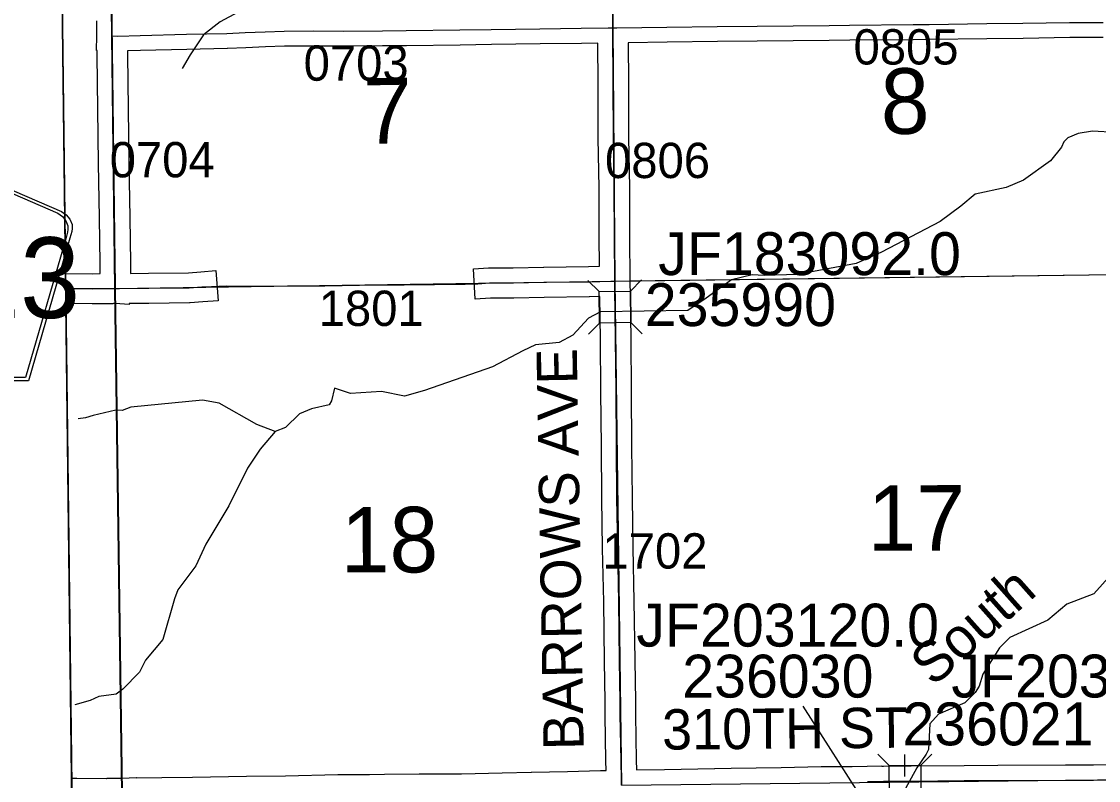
# Model space of a CAD drawing. Extents: x 23.6 to 68.7, y -63 to -29.
# Drawn here: x 32.621 to 34.757, y -54.733 to -53.228 of the extents above; entities that cross this region are included whole.
import ezdxf

# ---------------------------------------------------------------- set-up
doc = ezdxf.new("R2010")
doc.units = 0
for name, color, linetype in [('tdCoClipBndry', 7, 'Continuous'), ('tdCoCoBndry', 7, 'Continuous'), ('tdCoCoBndryPart', 7, 'Continuous'), ('tdCoHydroRiver', 7, 'Continuous'), ('tdCoHydroTxtLg', 7, 'Continuous'), ('tdCoSecRdNmbr', 7, 'Continuous'), ('tdCoSecRdTxt', 7, 'Continuous'), ('tdCoSecRteBand', 7, 'Continuous'), ('tdCoSecRteCL', 7, 'Continuous'), ('tdCoSectLine', 7, 'Continuous'), ('tdCoSectLinePart', 7, 'Continuous'), ('tdCoSectNmbr', 7, 'Continuous'), ('tdCoShieldCoRte', 7, 'Continuous'), ('tdCoStrucSec', 7, 'Continuous'), ('tdCoStrucSecCoName', 7, 'Continuous'), ('tdCoStrucSecFHWANum', 7, 'Continuous'), ('tdCoSurfAsphalt', 7, 'Continuous'), ('tdCoSurfGravel', 7, 'Continuous'), ('tdCoSurfLNO', 7, 'Continuous'), ('tdCoTwpBndryShd', 7, 'Continuous')]:
    doc.layers.add(name, color=color, linetype=linetype)

msp = doc.modelspace()

# ---------------------------------------------------------------- linework, layer by layer
at = {"layer": 'tdCoClipBndry'}
msp.add_lwpolyline([(56.8227, -57.553), (51.8233, -57.6334), (46.8056, -57.7041), (45.8081, -57.7131), (44.8328, -57.735), (43.8446, -57.7356), (42.8125, -57.7502), (36.856, -57.8104), (34.8462, -57.8398), (33.8615, -57.8433), (32.8589, -57.8556), (32.833, -57.8525), (32.8013, -57.8383), (32.7717, -57.8067), (32.7614, -57.7827), (32.7577, -57.7569), (32.6839, -51.7283), (32.6474, -49.7276), (32.6233, -45.7459), (32.6113, -44.7492), (32.588, -43.7493), (32.587, -43.0064), (32.5923, -42.7484), (32.5183, -35.7733)], dxfattribs=at)
at = {"layer": 'tdCoCoBndry'}
for p, q in [((32.8066, -53.7572), (32.7948, -52.7546)), ((32.7948, -52.7546), (32.8066, -53.7572)), ((32.8205, -54.758), (32.8066, -53.7572)), ((32.8066, -53.7572), (32.8205, -54.758))]:
    msp.add_line(p, q, dxfattribs=at)
for points in [[(32.6718, -40.7503), (32.6807, -41.745), (32.6923, -42.7489), (32.6875, -42.9908), (32.687, -43.0063), (32.6879, -43.7492), (32.7112, -44.7475), (32.7232, -45.7449), (32.73, -46.7351), (32.7344, -47.7196), (32.7414, -48.7221), (32.7473, -49.7257), (32.7682, -50.7257), (32.7838, -51.7268), (32.7945, -52.7546), (32.8063, -53.7572), (32.8202, -54.758), (32.8346, -55.7561), (32.8426, -56.756), (32.8576, -57.7557)], [(36.8552, -57.7104), (35.8554, -57.7251), (34.8462, -57.7399), (33.861, -57.7434), (32.858, -57.7557), (32.843, -56.756), (32.8349, -55.7561), (32.8205, -54.758), (32.8066, -53.7572), (32.7948, -52.7546), (32.7842, -51.7268), (32.7685, -50.7257), (32.7477, -49.7257), (32.7417, -48.7221), (32.7347, -47.7196), (32.7303, -46.7351), (32.7236, -45.745), (32.7116, -44.7475), (32.6883, -43.7492), (32.6873, -43.0063), (32.6879, -42.9908), (32.6927, -42.7489), (32.6811, -41.7451), (32.6722, -40.7503)], [(32.6474, -49.7276), (32.6839, -51.7283), (32.7577, -57.7564), (32.858, -57.7557), (32.843, -56.756), (32.8349, -55.7561), (32.8205, -54.758), (32.8066, -53.7572), (32.7948, -52.7546), (32.7842, -51.7268), (32.7685, -50.7257)]]:
    msp.add_lwpolyline(points, dxfattribs=at)
at = {"layer": 'tdCoCoBndryPart'}
msp.add_lwpolyline([(32.8067, -53.7876), (32.8198, -54.7285)], dxfattribs=at)
at = {"layer": 'tdCoHydroRiver'}
for points in [[(33.736, -52.7747), (33.7282, -52.7905), (33.7253, -52.8174), (33.7176, -52.8459), (33.6881, -52.9029), (33.6677, -52.9268), (33.5878, -53), (33.58, -53.0111), (33.5439, -53.0399), (33.4386, -53.0991), (33.3725, -53.1154), (33.2085, -53.1357), (33.1643, -53.1455), (33.1455, -53.1551), (33.1204, -53.1774), (33.0779, -53.1951), (33.015, -53.2288), (32.9821, -53.2543), (32.9556, -53.294), (32.94, -53.321)], [(34.8369, -53.4509), (34.7453, -53.4454), (34.7169, -53.4503), (34.6965, -53.4584)], [(34.6965, -53.4584), (34.6886, -53.4663), (34.684, -53.4774), (34.6621, -53.5044), (34.6087, -53.5427), (34.5741, -53.5572), (34.5127, -53.5704), (34.4845, -53.5943), (34.4436, -53.6246), (34.3273, -53.6855), (34.277, -53.708), (34.1604, -53.7295), (34.0941, -53.7316), (34.0704, -53.7302), (34.0294, -53.74), (33.9792, -53.7767), (33.9431, -53.8007), (33.7695, -53.8036), (33.7459, -53.8165), (33.7146, -53.8499), (33.6879, -53.8643), (33.6406, -53.8694), (33.6154, -53.8807), (33.5557, -53.9127), (33.4203, -53.9596), (33.3809, -53.9709), (33.3351, -53.9618), (33.2735, -53.9655), (33.2561, -53.9593), (33.2419, -53.9547), (33.2358, -53.98), (33.2311, -53.9879), (33.1964, -53.9961), (33.1728, -54.0058), (33.1446, -54.0328), (33.1242, -54.0409)], [(33.1242, -54.0409), (33.0878, -54.027), (33.0132, -53.985), (32.98, -53.9789), (32.8381, -53.9927), (32.8207, -53.9991), (32.8082, -53.9988)], [(32.8082, -53.9988), (32.7633, -54.0094), (32.7483, -54.0137), (32.7333, -54.0158)], [(33.1242, -54.0409), (33.0945, -54.0759), (33.0695, -54.1139), (33.0322, -54.1884), (32.9871, -54.2646), (32.9669, -54.3074), (32.931, -54.355), (32.9248, -54.3724), (32.9017, -54.4531), (32.8673, -54.4944), (32.8549, -54.5182), (32.822, -54.5516), (32.8091, -54.5619)], [(34.7823, -54.3243), (34.7479, -54.3625), (34.6944, -54.3834), (34.6568, -54.4153), (34.5813, -54.4491), (34.5609, -54.4698), (34.5282, -54.5221), (34.5205, -54.5459), (34.5127, -54.5585), (34.4924, -54.5792), (34.4404, -54.6017), (34.4232, -54.6208), (34.4205, -54.6714), (34.4158, -54.6809), (34.3971, -54.7079), (34.3675, -54.7618)], [(32.8091, -54.5619), (32.7742, -54.5661), (32.7571, -54.5746), (32.7271, -54.5832)]]:
    msp.add_lwpolyline(points, dxfattribs=at)
at = {"layer": 'tdCoSecRteBand'}
for points in [[(32.7083, -53.7274), (32.7616, -53.728), (32.7773, -53.7278), (32.7772, -53.7079), (32.7758, -53.6173), (32.7738, -53.5098), (32.7738, -53.5097), (32.7738, -53.5096), (32.7726, -53.4021), (32.7712, -53.2946), (32.7711, -53.2869), (32.7711, -53.2855), (32.7697, -53.2854), (32.7707, -53.2562), (32.7704, -53.2269)], [(32.7206, -54.7285), (32.7302, -54.7285), (32.7304, -54.7285), (32.7306, -54.7285), (32.7896, -54.729), (32.7896, -54.729), (32.7902, -54.7289), (32.7902, -54.7284), (32.8199, -54.728), (32.8495, -54.7271), (32.8495, -54.7271), (32.8496, -54.7271), (32.8496, -54.7277), (32.8994, -54.7272), (32.9601, -54.7262), (33.0674, -54.7244), (33.0675, -54.7244), (33.0676, -54.7244), (33.1448, -54.7236), (33.2487, -54.7213), (33.2489, -54.7213), (33.2491, -54.7213), (33.2815, -54.721), (33.3114, -54.7208), (33.3413, -54.7204), (33.3413, -54.7204), (33.4097, -54.7196), (33.41, -54.7196), (33.4102, -54.7196), (33.4938, -54.7198), (33.5748, -54.7178), (33.5748, -54.7178), (33.5748, -54.7178), (33.6322, -54.7164), (33.6324, -54.7164), (33.6325, -54.7164), (33.7039, -54.7153), (33.7694, -54.7133), (33.7694, -54.7133), (33.7695, -54.7133), (33.781, -54.713), (33.7805, -54.6937), (33.7805, -54.6936), (33.7805, -54.6936), (33.7788, -54.6032), (33.7787, -54.6028), (33.7787, -54.6024), (33.7789, -54.5765), (33.7776, -54.4962), (33.7776, -54.4961), (33.7776, -54.4961), (33.776, -54.3784), (33.7738, -54.273), (33.7738, -54.2729), (33.7738, -54.2728), (33.7722, -54.1736), (33.7722, -54.1735), (33.7722, -54.1734), (33.7715, -54.0708), (33.7705, -53.9613), (33.7695, -53.8582), (33.7685, -53.7733), (33.7475, -53.7739), (33.7473, -53.7739), (33.747, -53.7739), (33.6578, -53.7749), (33.5977, -53.7763), (33.5973, -53.7763), (33.597, -53.7763), (33.5523, -53.7763), (33.5512, -53.7764), (33.5213, -53.7783), (33.5175, -53.7184), (33.5474, -53.7165), (33.5495, -53.7164), (33.5504, -53.7163), (33.5514, -53.7163), (33.5966, -53.7163), (33.6566, -53.7149), (33.6568, -53.7149), (33.657, -53.7149), (33.7461, -53.7139), (33.7679, -53.7133), (33.7679, -53.7129), (33.7673, -53.6543), (33.7673, -53.6543), (33.7673, -53.6542), (33.7669, -53.5581), (33.7653, -53.4594), (33.7653, -53.4592), (33.7653, -53.4591), (33.7649, -53.3506), (33.7643, -53.2707), (33.7318, -53.2713), (33.7317, -53.2713), (33.7317, -53.2713), (33.65, -53.2725), (33.65, -53.2725), (33.65, -53.2725), (33.5533, -53.2738), (33.5533, -53.2738), (33.5533, -53.2738), (33.4913, -53.2746), (33.3848, -53.276), (33.3847, -53.276), (33.3847, -53.276), (33.3373, -53.2764), (33.3373, -53.2764), (33.3373, -53.2764), (33.2605, -53.277), (33.2604, -53.277), (33.2602, -53.277), (33.1994, -53.2768), (33.1428, -53.2772), (33.1053, -53.2782), (33.0662, -53.2799), (33.0661, -53.2799), (33.0661, -53.2799), (33.0296, -53.2815), (33.0293, -53.2815), (33.029, -53.2815), (32.9489, -53.2833), (32.8575, -53.2855), (32.8311, -53.2863), (32.8312, -53.2939), (32.8312, -53.2939), (32.8312, -53.2939), (32.8326, -53.4014), (32.8326, -53.4014), (32.8326, -53.4014), (32.8338, -53.5088), (32.8358, -53.6163), (32.8358, -53.6163), (32.8358, -53.6163), (32.8371, -53.7071), (32.8371, -53.7073), (32.8371, -53.7074), (32.8373, -53.7274), (32.8732, -53.7269), (32.8733, -53.7269), (32.8733, -53.7269), (32.9525, -53.726), (32.9766, -53.7242), (33.0065, -53.722), (33.011, -53.7818), (32.981, -53.784), (32.956, -53.7859), (32.9551, -53.786), (32.9542, -53.786), (32.874, -53.7869), (32.8347, -53.7874), (32.8345, -53.7891), (32.8066, -53.7872), (32.8041, -53.7874), (32.8033, -53.7874), (32.8025, -53.7875), (32.762, -53.788), (32.7617, -53.788), (32.7613, -53.788), (32.7091, -53.7874)], [(34.7669, -53.26), (34.7003, -53.2598), (34.6081, -53.2614), (34.608, -53.2614), (34.6079, -53.2614), (34.5363, -53.2622), (34.4217, -53.2636), (34.39, -53.264), (34.3899, -53.264), (34.3899, -53.264), (34.2641, -53.2652), (34.2235, -53.2658), (34.2234, -53.2658), (34.2233, -53.2658), (34.0805, -53.2669), (34.0017, -53.2679), (34.0017, -53.2679), (34.0017, -53.2679), (33.9018, -53.2691), (33.8243, -53.27), (33.8243, -53.27), (33.8243, -53.27), (33.8249, -53.3502), (33.8249, -53.3503), (33.8249, -53.3503), (33.8253, -53.4587), (33.8269, -53.5573), (33.8269, -53.5575), (33.8269, -53.5577), (33.8273, -53.6539), (33.8281, -53.7422), (33.8287, -53.7721), (33.8285, -53.7721), (33.8295, -53.8575), (33.8295, -53.8575), (33.8295, -53.8576), (33.8305, -53.9608), (33.8305, -53.9608), (33.8305, -53.9608), (33.8314, -54.0703), (33.8314, -54.0703), (33.8314, -54.0703), (33.8322, -54.1728), (33.8338, -54.2718), (33.836, -54.3773), (33.836, -54.3774), (33.836, -54.3775), (33.8376, -54.4952), (33.8389, -54.5759), (33.8389, -54.5762), (33.8389, -54.5766), (33.8388, -54.6024), (33.8405, -54.6923), (33.841, -54.7117), (33.8969, -54.7109), (33.996, -54.7091), (33.9961, -54.7091), (33.9962, -54.7091), (34.0291, -54.7087), (34.1281, -54.707), (34.2074, -54.7052), (34.2077, -54.7052), (34.2081, -54.7052), (34.2642, -54.7052), (34.2686, -54.7052), (34.2983, -54.7047), (34.328, -54.7037), (34.328, -54.7043), (34.3286, -54.7043), (34.3307, -54.7043), (34.3308, -54.7043), (34.331, -54.7043), (34.386, -54.704), (34.4909, -54.7032), (34.491, -54.7032), (34.491, -54.7032), (34.5579, -54.7028), (34.6918, -54.702), (34.6919, -54.702), (34.692, -54.702), (34.7474, -54.702), (34.8943, -54.6997)]]:
    msp.add_lwpolyline(points, dxfattribs=at)
at = {"layer": 'tdCoSecRteCL'}
for points in [[(32.8007, -53.2565), (32.7998, -53.1883), (32.7985, -53.0824), (32.7975, -52.975), (32.7961, -52.8667), (32.7949, -52.7616), (32.7939, -52.6641), (32.7926, -52.5588), (32.7914, -52.4576), (32.7896, -52.3498), (32.7884, -52.2737), (32.7888, -52.2569)], [(33.7941, -53.2403), (33.7934, -53.1567), (33.7922, -53.0441), (33.7916, -52.9421), (33.791, -52.8365), (33.7902, -52.7341), (33.7894, -52.6252), (33.7884, -52.5145), (33.7882, -52.493)], [(33.7941, -53.2403), (33.8021, -53.2403), (33.9015, -53.2391), (34.0013, -53.2379), (34.0802, -53.2369), (34.2231, -53.2358), (34.2637, -53.2352), (34.3896, -53.234), (34.4213, -53.2336), (34.536, -53.2322), (34.6076, -53.2314), (34.7001, -53.2298), (34.767, -53.23)], [(32.8007, -53.2565), (32.8121, -53.2569), (32.8567, -53.2555), (32.9482, -53.2533), (33.0283, -53.2515), (33.0648, -53.25), (33.1043, -53.2482), (33.1423, -53.2472), (33.1994, -53.2468), (33.2603, -53.247), (33.3371, -53.2464), (33.3844, -53.246), (33.4909, -53.2446), (33.5529, -53.2438), (33.6496, -53.2425), (33.7312, -53.2413), (33.7849, -53.2403), (33.7941, -53.2403)], [(33.7981, -53.7426), (33.7973, -53.6541), (33.7969, -53.5578), (33.7953, -53.4589), (33.7949, -53.3504), (33.7941, -53.2486), (33.7941, -53.2403)], [(32.8066, -53.7572), (32.8073, -53.746), (32.8071, -53.7076), (32.8058, -53.6168), (32.8038, -53.5093), (32.8026, -53.4018), (32.8012, -53.2942), (32.8007, -53.2565)], [(33.5493, -53.7464), (33.5514, -53.7463), (33.597, -53.7463), (33.6573, -53.7449), (33.7467, -53.7439), (33.7899, -53.7427), (33.7981, -53.7426)], [(33.8113, -54.7422), (33.8115, -54.7312), (33.8105, -54.693), (33.8087, -54.6026), (33.8089, -54.5764), (33.8076, -54.4957), (33.806, -54.3779), (33.8038, -54.2724), (33.8022, -54.1731), (33.8014, -54.0705), (33.8005, -53.961), (33.7995, -53.8579), (33.7983, -53.7576), (33.7981, -53.7426)], [(32.7087, -53.7574), (32.7617, -53.758), (32.8022, -53.7575), (32.8066, -53.7572)], [(32.8066, -53.7572), (32.8158, -53.7577), (32.8736, -53.7569), (32.9538, -53.756), (32.9788, -53.7541)], [(34.299, -54.7347), (34.3311, -54.7343), (34.3862, -54.734), (34.4912, -54.7332), (34.558, -54.7328), (34.692, -54.732), (34.7476, -54.732), (34.8948, -54.7297), (34.9372, -54.7289), (35.0976, -54.7291), (35.2363, -54.7279), (35.2866, -54.7283), (35.4622, -54.7269), (35.6538, -54.7249), (35.8005, -54.7233), (35.8156, -54.7235)]]:
    msp.add_lwpolyline(points, dxfattribs=at)
at = {"layer": 'tdCoSectLine'}
for points in [[(33.7899, -52.7341), (33.7978, -53.7426)], [(32.7945, -52.7546), (32.8063, -53.7572)], [(32.8063, -53.7572), (33.7978, -53.7426)], [(33.7978, -53.7426), (34.7885, -53.7294)], [(33.7978, -53.7426), (33.811, -54.7422)], [(32.7087, -53.7577), (32.8063, -53.7572)], [(32.8063, -53.7572), (32.8202, -54.758)], [(33.811, -54.7422), (34.8144, -54.7309)]]:
    msp.add_lwpolyline(points, dxfattribs=at)
at = {"layer": 'tdCoSectLinePart'}
for points in [[(33.8281, -53.7422), (34.7885, -53.7294)], [(32.8067, -53.7876), (32.8198, -54.7285)]]:
    msp.add_lwpolyline(points, dxfattribs=at)
at = {"layer": 'tdCoShieldCoRte'}
for points in [[(32.3954, -53.9402), (32.3135, -53.6573), (32.3096, -53.6441), (32.3089, -53.6382), (32.3089, -53.6304), (32.3131, -53.6201), (32.3204, -53.6116), (32.33, -53.6049), (32.4973, -53.5326), (32.5048, -53.531), (32.5152, -53.53), (32.5256, -53.531), (32.5331, -53.5326), (32.7004, -53.6049), (32.71, -53.6116), (32.7173, -53.6201), (32.7215, -53.6304), (32.7215, -53.6382), (32.7208, -53.6441), (32.7169, -53.6573), (32.635, -53.9402)], [(32.4013, -53.9338), (32.3216, -53.6586), (32.3178, -53.6459), (32.3171, -53.6403), (32.3171, -53.6328), (32.3212, -53.6229), (32.3282, -53.6147), (32.3374, -53.6083), (32.498, -53.5389), (32.5052, -53.5373), (32.5152, -53.5364), (32.5252, -53.5373), (32.5324, -53.5389), (32.693, -53.6083), (32.7022, -53.6147), (32.7092, -53.6229), (32.7133, -53.6328), (32.7133, -53.6403), (32.7126, -53.6459), (32.7088, -53.6586), (32.6291, -53.9338)]]:
    msp.add_lwpolyline(points, close=True, dxfattribs=at)
at = {"layer": 'tdCoStrucSec'}
for p, q in [((33.7667, -53.7633), (33.7443, -53.7414)), ((33.8293, -53.7625), (33.8512, -53.7401)), ((33.7675, -53.8258), (33.7456, -53.8482)), ((33.8301, -53.8251), (33.8524, -53.847)), ((34.3423, -54.7029), (34.32, -54.6809)), ((34.4049, -54.7026), (34.4269, -54.6804))]:
    msp.add_line(p, q, dxfattribs=at)
for points in [[(33.7675, -53.8258), (33.7667, -53.7633), (33.8293, -53.7625), (33.8301, -53.8251)], [(34.3423, -54.7029), (34.4049, -54.7026), (34.4052, -54.7652), (34.3426, -54.7655)]]:
    msp.add_lwpolyline(points, close=True, dxfattribs=at)
at = {"layer": 'tdCoStrucSecFHWANum'}
for p, q in [((34.1709, -54.5855), (34.298, -54.7841)), ((34.3724, -54.6817), (34.3724, -54.7251))]:
    msp.add_line(p, q, dxfattribs=at)
at = {"layer": 'tdCoSurfAsphalt'}
msp.add_lwpolyline([(34.4912, -54.7332), (34.558, -54.7328), (34.692, -54.732), (34.7476, -54.732), (34.8948, -54.7297), (34.9372, -54.7289), (35.0976, -54.7291), (35.2363, -54.7279), (35.2866, -54.7283), (35.4622, -54.7269), (35.6538, -54.7249), (35.8005, -54.7233), (35.8156, -54.7235), (35.8485, -54.7237), (35.9953, -54.7218), (36.0479, -54.7212), (36.2097, -54.7198), (36.3648, -54.7178), (36.4107, -54.7176), (36.5587, -54.7153), (36.7371, -54.7121)], dxfattribs=at)
at = {"layer": 'tdCoSurfGravel'}
for points in [[(32.8066, -53.7572), (32.8073, -53.746), (32.8071, -53.7076), (32.8058, -53.6168), (32.8038, -53.5093), (32.8026, -53.4018), (32.8012, -53.2942), (32.8007, -53.2565), (32.7998, -53.1883), (32.7985, -53.0824), (32.7975, -52.975), (32.7961, -52.8667), (32.7949, -52.7616), (32.7939, -52.6641), (32.7926, -52.5588), (32.7914, -52.4576), (32.7896, -52.3498), (32.7884, -52.2737), (32.7888, -52.2569)], [(33.8113, -54.7422), (33.8115, -54.7312), (33.8105, -54.693), (33.8087, -54.6026), (33.8089, -54.5764), (33.8076, -54.4957), (33.806, -54.3779), (33.8038, -54.2724), (33.8022, -54.1731), (33.8014, -54.0705), (33.8005, -53.961), (33.7995, -53.8579), (33.7983, -53.7576), (33.7981, -53.7426), (33.7973, -53.6541), (33.7969, -53.5578), (33.7953, -53.4589), (33.7949, -53.3504), (33.7941, -53.2486), (33.7941, -53.2403), (33.7934, -53.1567)], [(32.8007, -53.2565), (32.8121, -53.2569), (32.8567, -53.2555), (32.9482, -53.2533), (33.0283, -53.2515), (33.0648, -53.25), (33.1043, -53.2482), (33.1423, -53.2472), (33.1994, -53.2468), (33.2603, -53.247), (33.3371, -53.2464), (33.3844, -53.246), (33.4909, -53.2446), (33.5529, -53.2438), (33.6496, -53.2425), (33.7312, -53.2413), (33.7849, -53.2403), (33.7941, -53.2403), (33.8021, -53.2403), (33.9015, -53.2391), (34.0013, -53.2379), (34.0802, -53.2369), (34.2231, -53.2358), (34.2637, -53.2352), (34.3896, -53.234), (34.4213, -53.2336), (34.536, -53.2322), (34.6076, -53.2314), (34.7001, -53.2298), (34.767, -53.23)], [(33.5493, -53.7464), (33.5514, -53.7463), (33.597, -53.7463), (33.6573, -53.7449), (33.7467, -53.7439), (33.7899, -53.7427), (33.7981, -53.7426)], [(32.7087, -53.7574), (32.7617, -53.758), (32.8022, -53.7575), (32.8066, -53.7572)], [(32.8066, -53.7572), (32.8158, -53.7577), (32.8736, -53.7569), (32.9538, -53.756), (32.9788, -53.7541)]]:
    msp.add_lwpolyline(points, dxfattribs=at)
at = {"layer": 'tdCoSurfLNO'}
for p, q in [((33.5265, -53.7479), (33.5493, -53.7464)), ((32.9788, -53.7541), (32.983, -53.7538)), ((32.983, -53.7538), (33.0278, -53.7522)), ((33.0278, -53.7522), (33.0789, -53.7526)), ((33.0789, -53.7526), (33.1489, -53.752)), ((33.1489, -53.752), (33.2231, -53.7518)), ((33.2231, -53.7518), (33.3257, -53.7504)), ((33.3257, -53.7504), (33.38, -53.7498)), ((33.38, -53.7498), (33.5011, -53.7485)), ((33.5011, -53.7485), (33.5265, -53.7479))]:
    msp.add_line(p, q, dxfattribs=at)
at = {"layer": 'tdCoTwpBndryShd'}
msp.add_lwpolyline([(32.8576, -57.7557), (32.8426, -56.756), (32.8346, -55.7561), (32.8202, -54.758), (32.8063, -53.7572), (32.7945, -52.7546), (32.7838, -51.7268), (32.7682, -50.7257), (32.7473, -49.7257), (32.7414, -48.7221), (32.7344, -47.7196), (32.73, -46.7351), (32.7232, -45.7449), (32.7112, -44.7475), (32.6879, -43.7492), (32.687, -43.0063), (32.6875, -42.9908), (32.6923, -42.7489), (32.6807, -41.745), (32.6718, -40.7503)], dxfattribs=at)

# ---------------------------------------------------------------- texts
at = {"layer": 'tdCoHydroTxtLg'}
msp.add_text('South', height=0.08, rotation=41.6956, dxfattribs=at).set_placement((34.4297, -54.5487))
at = {"layer": 'tdCoSecRdNmbr'}
for s, rotation, p in [('0805', 0.0271, (34.2716, -53.3133)), ('0703', 0.0263, (33.1808, -53.3454)), ('0704', 0.026, (32.7961, -53.537)), ('0806', 0.0267, (33.7787, -53.5385)), ('1801', 0.0263, (33.2107, -53.8317)), ('1702', 0.0267, (33.7736, -54.3128))]:
    msp.add_text(s, height=0.07, rotation=rotation, dxfattribs=at).set_placement(p)
at = {"layer": 'tdCoSecRdTxt'}
for s, rotation, p in [('BARROWS AVE', 91, (33.7365, -54.672)), ('310TH ST', 0.4602, (33.8921, -54.6718))]:
    msp.add_text(s, height=0.08, rotation=rotation, dxfattribs=at).set_placement(p)
at = {"layer": 'tdCoSectNmbr'}
for s, rotation, p in [('8', 1.027, (34.3264, -53.4516)), ('7', 1.0263, (33.3001, -53.4707)), ('17', 0.027, (34.2993, -54.2774)), ('18', 0.0262, (33.2545, -54.3204))]:
    msp.add_text(s, height=0.13, rotation=rotation, dxfattribs=at).set_placement(p)
at = {"layer": 'tdCoShieldCoRte'}
msp.add_text('T23', height=0.16, dxfattribs=at).set_placement((32.3686, -53.8159))
at = {"layer": 'tdCoStrucSecCoName'}
for s, p in [('JF183092.0', (33.8842, -53.7308)), ('JF203120.0', (33.8408, -54.4674)), ('JF203118.0', (34.4657, -54.5683))]:
    msp.add_text(s, height=0.085, dxfattribs=at).set_placement(p)
at = {"layer": 'tdCoStrucSecFHWANum'}
for s, p in [('235990', (33.8575, -53.8319)), ('236030', (33.9318, -54.5685)), ('236021', (34.3684, -54.6632))]:
    msp.add_text(s, height=0.085, dxfattribs=at).set_placement(p)

doc.saveas('drawing.dxf')
